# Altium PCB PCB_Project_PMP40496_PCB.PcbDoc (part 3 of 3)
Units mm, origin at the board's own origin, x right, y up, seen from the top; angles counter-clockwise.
Board outline 140 x 100 mm, 4 copper layers (Top Layer, Signal Layer 1, Signal Layer 2, Bottom Layer), stack 1.565 mm thick; 186 components, 128 nets, 605 pads, 270 vias.
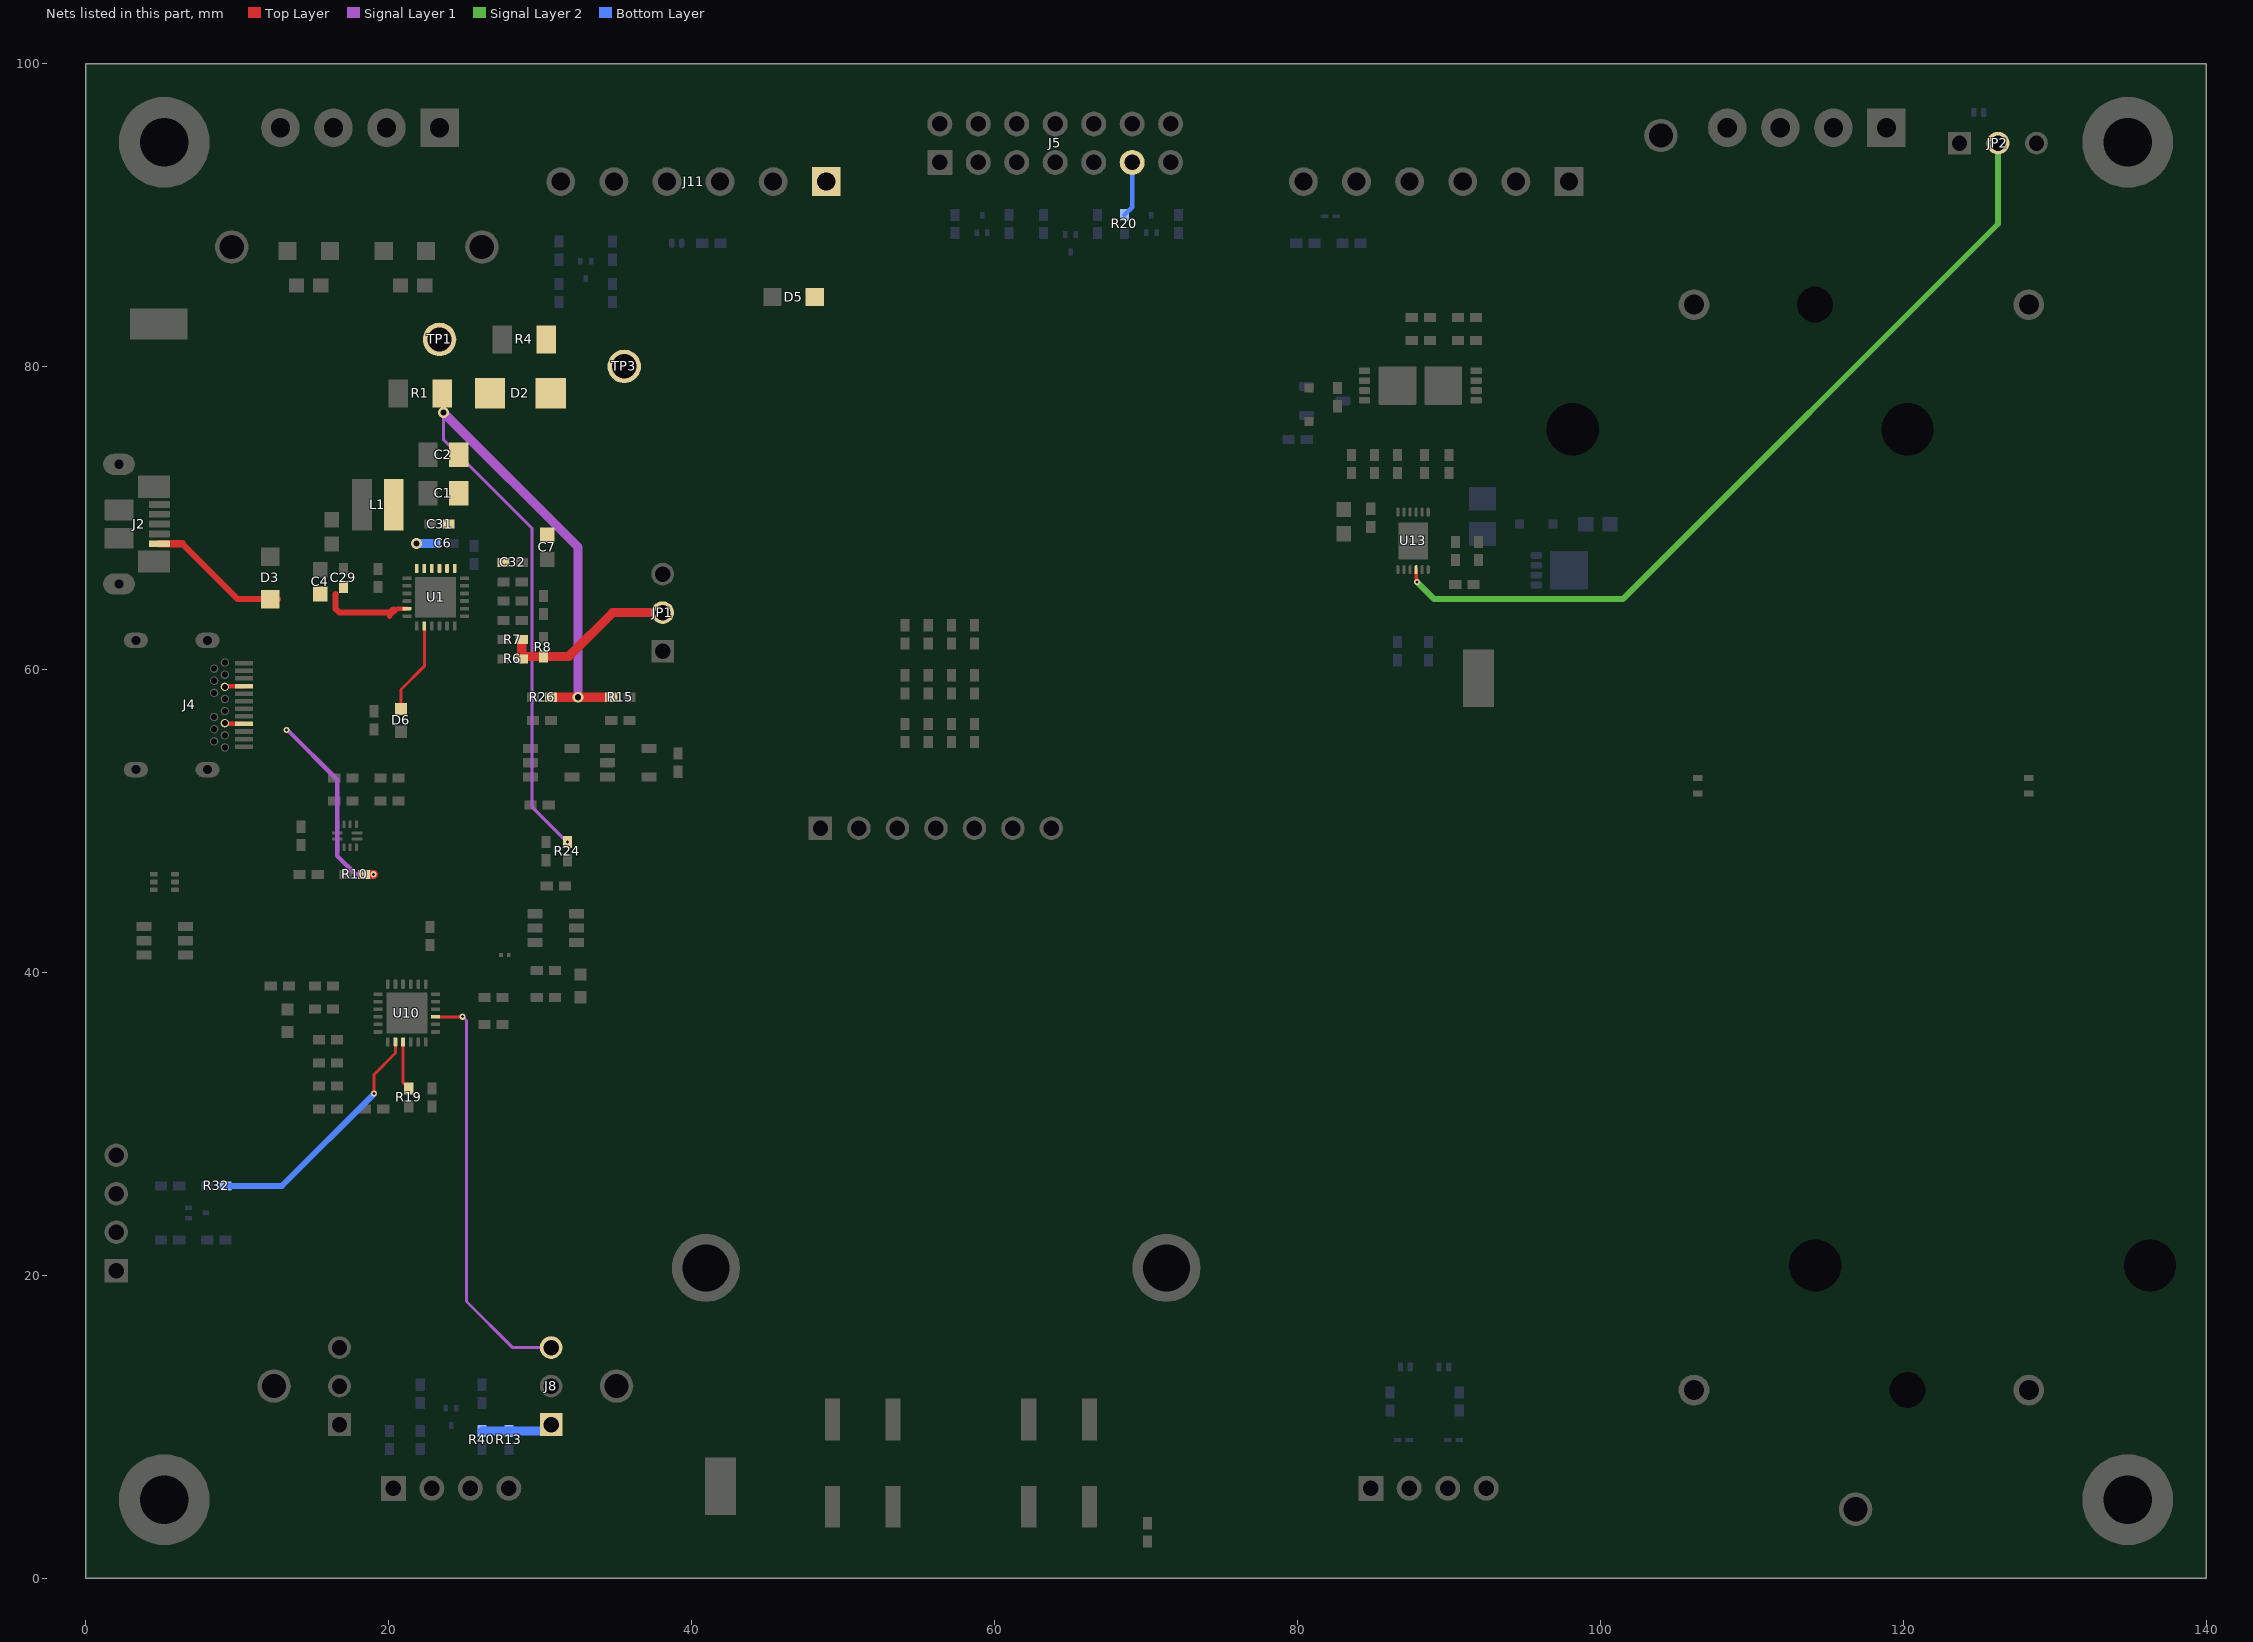
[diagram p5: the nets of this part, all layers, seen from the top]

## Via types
v1: diameter 0.406, hole 0.203, Top Layer to Bottom Layer, 92 vias
v2: diameter 0.711, hole 0.406, Top Layer to Bottom Layer, 89 vias
v3: diameter 0.9, hole 0.6, Top Layer to Bottom Layer, tented top, 59 vias
v4: diameter 0.5, hole 0.2, Top Layer to Bottom Layer, 27 vias
v5: diameter 0.5, hole 0.2, Top Layer to Bottom Layer, tented both sides, 3 vias

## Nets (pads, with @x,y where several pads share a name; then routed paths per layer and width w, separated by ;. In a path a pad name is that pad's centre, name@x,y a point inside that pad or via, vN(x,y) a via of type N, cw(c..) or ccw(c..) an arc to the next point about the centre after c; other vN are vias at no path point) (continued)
SDA_EXT: J8.1 R13.1 R40.2 | length 4.7
  Bottom Layer w0.6: R40.2@26.162,9.744 30.318,9.744 J8.1@30.734,10.16
SDA_MCU: J8.3 U10.9 | length 27.5
  Top Layer w0.2: U10.9@23.109,37.075 24.883,37.075 v1(24.892,37.084)
  Signal Layer 1 w0.2: v1(24.892,37.084) 25.146,36.83 25.146,18.288 28.194,15.24 J8.3@30.734,15.24
STAT: D6.2 U1.2 | length 6.1
  Top Layer w0.2: D6.2@20.828,57.392 20.828,58.674 22.364,60.21 U1.2@22.364,62.87
SW: C6.2 L1.2 U1.17 U1.18 | length 1.2
  Bottom Layer w0.6: v2(21.844,68.326) C6.2@23.022,68.326
TEST: R32.2 U10.2 | length 16.3
  Top Layer w0.2: v1(19.05,32.004) 19.05,33.274 20.459,34.683 U10.2@20.459,35.425
  Bottom Layer w0.4: R32.2@9.236,25.908 12.954,25.908 v1(19.05,32.004)
TS1: JP2.2 U13.4 | length 55.2
  Top Layer w0.22: U13.4@87.83,66.588 87.83,65.84 v1(87.884,65.786)
  Signal Layer 2 w0.4: v1(87.884,65.786) 89.027,64.643 101.473,64.643 126.238,89.408 JP2.2@126.238,94.742
TS_CHG: JP1.2 R6.1 R7.1 R8.2 | length 11.8
  Top Layer w0.6: R7.1@28.794,61.976 R6.1@28.794,60.706 28.956,60.868 R8.2@30.226,60.868 31.912,60.868 34.798,63.754 JP1.2@38.1,63.754
TX: J5.11 R20.1 | length 3.7
  Bottom Layer w0.3: R20.1@68.58,90.008 69.088,90.516 J5.11@69.088,93.472
TX_MCU: R19.2 U10.3 | length 3.2
  Top Layer w0.2: U10.3@20.959,35.425 20.959,32.727 R19.2@21.336,32.35
VBAT: C7.1 C32.1 D2.2 D5.1 J11.1 R4.2 TP3.1 U1.13 U1.14
VBUS: C4.1 C29.1 D3.1 J2.1 J4.A4 J4.A9 J4.B4 J4.B9 R10.1 U1.23 | length 31.5
  Top Layer w0.3: J4.B4@9.193,56.458 9.243,56.408 J4.A9@10.453,56.408 ; J4.B9@9.193,58.858 9.243,58.908 J4.A4@10.453,58.908 ; 20.066,63.5 20.586,64.02 U1.23@21.214,64.02
  Top Layer w0.4: 6.38,68.296 10.036,64.64 D3.1@12.7,64.64 ; 16.51,64.986 16.51,64.008 16.764,63.754 20.104,63.754 20.32,63.97
  Top Layer w0.5: J2.1@4.872,68.296 6.38,68.296
  Top Layer w0.6: R10.1@18.38,46.482 v1(18.999,46.482)
  Signal Layer 1 w0.3: v1(13.271,56.007) 13.335,56.007 16.622,52.72 16.622,47.694 17.834,46.482 v1(18.999,46.482)
VSYS: C1.1 C2.1 C31.1 D2.1 R1.1 R15.1 R24.1 R26.1 TP1.1 U1.15 U1.16 | length 57.9
  Top Layer w0.6: R26.1@30.734,58.166 v2(32.512,58.166) R15.1@34.456,58.166
  Signal Layer 1 w0.2: v2(23.622,76.962) 23.622,75.184 29.464,69.342 29.464,50.949 v1(31.807,48.606)
  Signal Layer 1 w0.6: v2(23.622,76.962) 32.512,68.072 v2(32.512,58.166)
pads on no net: BT1.MH1 BT1.MH2 BT1.MH3 BT2.MH1 BT2.MH2 BT2.MH3 J4.A2 J4.A3 J4.A8 J4.A10 J4.A11 J4.B2 J4.B3 J4.B8 J4.B10 J4.B11 J9.4 J15.4 Q2.9@85.738,78.077 Q2.9@85.738,79.402 Q2.9@86.278,78.74 Q2.9@86.614,78.077 Q2.9@86.614,79.402 Q2.9@87.125,77.765 Q2.9@87.125,78.415 Q2.9@87.125,79.065 Q2.9@87.125,79.715 Q3.9@89.093,77.765 Q3.9@89.093,78.415 Q3.9@89.093,79.065 Q3.9@89.093,79.715 Q3.9@89.604,78.078 Q3.9@89.604,79.403 Q3.9@89.941,78.74 Q3.9@90.48,78.078 Q3.9@90.48,79.403 Q5.9@97.07,65.886 Q5.9@97.07,67.211 Q5.9@97.609,66.548 Q5.9@97.946,65.886 Q5.9@97.946,67.211 Q5.9@98.457,65.573 Q5.9@98.457,66.223 Q5.9@98.457,66.873 Q5.9@98.457,67.523 SH-JP1.0 SH-JP2.0 SH-JP3.0 SH-JP4.0 U1.10 U1.25@22.419,64.075 U1.25@22.419,65.465 U1.25@23.809,64.075 U1.25@23.809,65.465 U4.4 U8.4 U8.5 U10.16 U10.25@20.514,36.63 U10.25@20.514,38.02 U10.25@21.904,36.63 U10.25@21.904,38.02 U15.1S U15.2S U16.1S U16.2S U17.1S U17.2S U18.1S U18.2S

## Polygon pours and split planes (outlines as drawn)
GND on Top Layer "TOP_LAYER_GND_P106" (solid, remove dead copper, pour order 106): 2.505,99.481 71.593,99.481 73.625,97.449 73.625,3.215 71.593,1.183 3.521,1.183 0.473,4.231 0.473,97.449
VBAT on Top Layer "TOP_LAYER_VBAT_P104" (solid, remove dead copper, pour order 104): 44.196,83.312 46.228,83.312 46.736,83.82 46.736,96.52 48.26,98.044 53.086,98.044 54.61,96.52 54.61,75.692 52.832,73.914 44.196,73.914
VBUS on Top Layer "TOP_LAYER_VBUS_P102" (solid, remove dead copper, pour order 102): 5.842,68.58 9.144,68.58 11.938,65.786 17.272,65.786 17.526,65.532 17.526,64.482 17.746,64.262 21.336,64.262 21.59,64.008 21.59,63.754 21.336,63.5 20.706,63.5 20.574,63.368 20.574,61.214 19.558,60.198 17.907,60.198 13.208,55.499 9.906,55.499 9.906,64.008 5.842,68.072
VBAT on Top Layer "TOP_LAYER_VBAT_P094" (solid, remove dead copper, pour order 94): 24.638,67.564 29.21,72.136 29.21,82.296 30.226,83.312 45.212,83.312 45.212,73.914 40.132,73.914 34.544,68.326 28.956,68.326 28.194,67.564
LOAD2 on Top Layer "TOP_LAYER_LOAD2_P092" (solid, remove dead copper, pour order 92): 21.844,98.298 22.606,99.06 28.194,99.06 28.956,98.298 28.956,80.772 28.702,80.518 25.4,80.518 25.146,80.772 25.146,82.989 24.442,83.693 22.733,83.693 21.844,84.582
VSYS on Top Layer "TOP_LAYER_VSYS_P090" (solid, remove dead copper, pour order 90): 23.622,74.168 23.114,74.676 22.352,74.676 21.844,75.184 21.844,82.677 22.479,83.312 24.384,83.312 24.892,82.804 24.892,80.518 25.4,80.01 28.702,80.01 28.956,79.756 28.956,72.136 25.908,69.088 23.622,69.088
LOAD1 on Top Layer "TOP_LAYER_LOAD1_P088" (solid, remove dead copper, pour order 88): 8.382,99.06 13.755,99.06 14.478,98.337 14.478,83.82 17.78,80.518 20.828,80.518 21.59,79.756 21.59,76.708 20.828,75.946 13.462,75.946 7.62,81.788 7.62,98.298
VBAT on Top Layer "TOP_LAYER_VBAT_P086" (solid, remove dead copper, pour order 86): 23.622,66.294 23.622,67.31 24.384,68.072 25.146,68.072 26.416,69.342 28.194,69.342 28.194,67.056 27.94,66.802 25.908,66.802 25.4,66.294
VSYS on Top Layer "TOP_LAYER_VSYS_P084" (solid, remove dead copper, pour order 84): 22.606,66.294 22.606,68.58 23.622,69.596 23.622,74.168 26.162,74.168 26.162,69.342 25.146,68.326 24.638,68.326 23.622,67.31 23.622,66.294
SW on Top Layer "TOP_LAYER_SW_P082" (solid, remove dead copper, pour order 82): 21.712,66.294 21.574,66.294 21.574,66.31 20.32,67.564 20.32,68.072 19.304,69.088 19.304,72.39 19.558,72.644 21.082,72.644 21.336,72.39 21.336,69.85 22.606,68.58 22.606,66.294
GND on Top Layer "TOP_LAYER_GND_P080" (solid, remove dead copper, pour order 80): 20.574,65.278 19.812,66.04 15.494,66.04 15.494,68.834 19.304,68.834 20.066,68.072 20.066,67.564 21.336,66.294 21.844,66.294 21.844,65.278
VBUS on Top Layer "TOP_LAYER_VBUS_P076" (solid, remove dead copper, pour order 76): 15.494,65.786 17.272,65.786 17.272,64.516 17.526,64.262 21.336,64.262 21.59,64.008 21.59,63.754 21.336,63.5 20.574,63.5 19.304,62.23 16.256,62.23 15.494,62.992
PMID on Top Layer "TOP_LAYER_PMID_P074" (solid, remove dead copper, pour order 74): 18.034,66.04 17.78,65.786 17.78,64.516 18.034,64.262 21.336,64.262 21.59,64.516 21.59,65.024 21.336,65.278 20.574,65.278 19.812,66.04
GND1 on Top Layer "TOP_LAYER_GND1_P072" (solid, remove dead copper, pour order 72): 83.312,99.314 81.788,97.79 81.788,3.048 84.074,0.762 137.414,0.762 138.938,2.286 138.938,98.044 137.668,99.314
NetBT1_2 on Top Layer "TOP_LAYER_NETBT1_2_P058" (solid, remove dead copper, pour order 58): 113.03,7.874 114.046,6.858 114.046,3.302 114.808,2.54 118.872,2.54 119.634,3.302 119.634,6.858 120.65,7.874
NetBT1_1 on Top Layer "TOP_LAYER_NETBT1_1_P002" (solid, remove dead copper, pour order 2): 92.202,79.248 92.456,79.502 92.456,80.264 91.44,81.28 91.44,84.836 92.964,86.36 107.413,86.36 109.728,84.045 109.728,77.216 108.458,75.946 92.456,75.946 91.44,76.962 91.44,78.994 91.694,79.248
NetBT1_2 on Top Layer "TOP_LAYER_NETBT1_2_P004" (solid, remove dead copper, pour order 4): 104.14,18.796 128.27,18.796 130.556,16.51 130.556,8.636 129.54,7.62 103.378,7.62 102.362,8.636 102.362,17.018
NetBT1_1 on Top Layer "TOP_LAYER_NETBT1_1_P006" (solid, remove dead copper, pour order 6): 101.092,99.314 108.966,99.314 109.728,98.552 109.728,87.122 109.728,86.106 109.728,83.786 99.06,83.851 99.06,86.106 100.33,87.376 100.33,98.552
NetQ2_5 on Top Layer "TOP_LAYER_NETQ2_5_P022" (solid, remove dead copper, pour order 22): 85.344,80.264 90.678,80.264 90.932,80.01 90.932,77.47 90.678,77.216 85.344,77.216 85.09,77.47 85.09,80.01
NetQ2_4 on Top Layer "TOP_LAYER_NETQ2_4_P030" (solid, remove dead copper, pour order 30): 82.296,77.978 84.836,77.978 84.836,76.708 82.296,76.708 82.042,76.962 82.042,77.724
PACK+ on Top Layer "TOP_LAYER_PACK+_P038" (solid, remove dead copper, pour order 38): 77.216,97.79 78.74,99.314 88.9,99.314 89.916,98.298 89.916,84.582 89.408,84.074 88.532,84.074 84.831,80.373 84.831,78.481 84.535,78.185 77.855,78.185 77.216,78.824
NetBT1_2 on Top Layer "TOP_LAYER_NETBT1_2_P040" (solid, remove dead copper, pour order 40): 110.236,98.552 110.998,99.314 116.078,99.314 117.094,98.298 117.094,93.726 123.444,87.376 123.444,81.28 111.252,81.28 110.236,82.296
NetBT1_2 on Top Layer "TOP_LAYER_NETBT1_2_P044" (solid, pour order 44): 111.252,81.28 111.252,20.574 108.966,18.288 126.492,18.288 123.444,21.336 123.444,81.28
GND2 on Top Layer "TOP_LAYER_GND2_P048" (solid, remove dead copper, pour order 48): 127.762,52.324 129.032,52.324 129.286,52.07 129.286,51.562 129.032,51.308 127.762,51.308 127.508,51.562 127.508,52.07
NetJP2_3 on Top Layer "TOP_LAYER_NETJP2_3_P050" (solid, remove dead copper, pour order 50): 128.143,95.631 129.413,95.631 129.667,95.377 129.667,94.107 129.54,93.98 128.016,93.98 127.889,94.107 127.889,95.377
TS1 on Top Layer "TOP_LAYER_TS1_P052" (solid, remove dead copper, pour order 52): 125.603,95.631 126.873,95.631 127.127,95.377 127.127,94.107 127,93.98 125.476,93.98 125.349,94.107 125.349,95.377
PMID on Top Layer "TOP_LAYER_PMID_P114" (solid, remove dead copper, pour order 114): 17.272,72.644 18.796,72.644 19.05,72.39 19.05,69.342 18.796,69.088 15.748,69.088 15.494,69.342 15.494,70.866
PMID on Bottom Layer "BOTTOM_LAYER_PMID_P098" (solid, remove dead copper, pour order 98): 17.272,72.644 20.32,72.644 20.574,72.39 20.574,64.629 20.207,64.262 17.78,64.262 17.526,64.516 17.526,68.326 16.764,69.088 16.764,72.136
GND1 on Bottom Layer "BOTTOM_LAYER_GND1_P070" (solid, remove dead copper, pour order 70): 78.74,70.358 81.788,67.31 81.788,3.048 84.074,0.762 137.414,0.762 138.938,2.286 138.938,98.044 137.668,99.314
NetR72_2 on Bottom Layer "BOTTOM_LAYER_NETR72_2_P068" (solid, remove dead copper, pour order 68): 90.17,11.938 89.916,12.192 89.916,13.97 90.17,14.224 91.186,14.224 91.44,13.97 91.44,12.192 91.186,11.938
NetR74_2 on Bottom Layer "BOTTOM_LAYER_NETR74_2_P066" (solid, remove dead copper, pour order 66): 85.598,11.938 85.344,12.192 85.344,13.97 85.598,14.224 86.614,14.224 86.868,13.97 86.868,12.192 86.614,11.938
SDA1 on Bottom Layer "BOTTOM_LAYER_SDA1_P064" (solid, remove dead copper, pour order 64): 89.154,4.826 88.9,5.08 88.9,8.382 89.154,8.636 90.932,8.636 90.932,9.525 89.662,9.525 89.662,11.176 89.916,11.43 91.694,11.43 91.948,11.176 91.948,7.62 91.186,6.858 91.186,5.08 90.932,4.826
SCL1 on Bottom Layer "BOTTOM_LAYER_SCL1_P062" (solid, remove dead copper, pour order 62): 87.884,4.826 88.392,5.334 88.392,8.382 88.138,8.636 86.487,8.636 86.36,8.763 86.36,9.525 87.63,9.525 87.63,11.176 87.376,11.43 85.598,11.43 85.344,11.176 85.344,7.874 86.106,7.112 86.106,5.334 86.614,4.826
NetBT2_2 on Bottom Layer "BOTTOM_LAYER_NETBT2_2_P008" (solid, remove dead copper, pour order 8): 114.3,99.06 116.332,99.06 117.094,98.298 117.094,93.472 118.364,92.202 130.048,92.202 133.604,88.646 133.604,80.518 131.572,78.486 118.274,78.486 115.57,81.19 115.57,84.328 113.792,86.106 113.792,98.552
NetBT2_2 on Bottom Layer "BOTTOM_LAYER_NETBT2_2_P012" (solid, remove dead copper, pour order 12): 96.52,67.818 97.028,68.326 101.092,68.326 108.712,75.946 108.712,87.63 120.142,87.63 120.142,78.74 118.618,77.216 118.618,70.612 113.03,65.024 97.028,65.024 96.52,65.532
NetBT2_2 on Bottom Layer "BOTTOM_LAYER_NETBT2_2_P014" (solid, pour order 14): 108.712,88.392 113.792,93.472 115.824,93.472 115.824,87.122 108.712,87.122
GND2 on Bottom Layer "BOTTOM_LAYER_GND2_P016" (solid, remove dead copper, pour order 16): 94.488,69.85 94.996,69.342 94.996,67.31 95.25,67.056 96.012,67.056 96.266,66.802 96.266,65.278 96.012,65.024 90.932,65.024 90.678,65.278 90.678,69.596 90.932,69.85
GND2 on Bottom Layer "BOTTOM_LAYER_GND2_P020" (solid, remove dead copper, pour order 20): 86.614,69.596 86.868,69.85 91.17,69.85 91.17,67.2 86.756,67.198 86.614,67.34
NetQ2_5 on Bottom Layer "BOTTOM_LAYER_NETQ2_5_P028" (solid, remove dead copper, pour order 28): 85.344,80.264 90.678,80.264 90.932,80.01 90.932,77.47 90.678,77.216 85.344,77.216 85.09,77.47 85.09,80.01
PACK+ on Bottom Layer "BOTTOM_LAYER_PACK+_P034" (solid, pour order 34): 78.74,93.726 81.28,93.726 81.534,93.472 81.534,89.154 81.083,88.703 80.829,88.703 80.518,88.392 80.518,87.884 80.264,87.63 78.994,87.63 78.486,88.138 78.486,93.472
GND1 on Bottom Layer "BOTTOM_LAYER_GND1_P036" (solid, remove dead copper, pour order 36): 100.584,70.104 106.426,75.946 106.426,98.044 105.156,99.314 78.74,99.314 77.216,97.79 77.216,71.882 78.994,70.104
GND2 on Bottom Layer "BOTTOM_LAYER_GND2_P046" (solid, remove dead copper, pour order 46): 90.678,65.278 90.678,57.658 90.932,57.404 95.592,57.404 96.266,58.078 96.266,65.278
NetJ14_1 on Bottom Layer "BOTTOM_LAYER_NETJ14_1_P054" (solid, remove dead copper, pour order 54): 123.063,95.631 124.333,95.631 124.587,95.377 124.587,94.107 124.46,93.98 122.936,93.98 122.809,94.107 122.809,95.377
NetJ14_1 on Bottom Layer "BOTTOM_LAYER_NETJ14_1_P056" (solid, remove dead copper, pour order 56): 122.428,97.028 122.682,97.282 124.46,97.282 124.714,97.028 124.714,94.234 124.46,93.98 122.682,93.98 122.428,94.234
GND on Bottom Layer "BOTTOM_LAYER_GND_P126" (solid, remove dead copper, pour order 126): 2.505,99.481 71.593,99.481 73.625,97.449 73.625,3.215 71.593,1.183 3.521,1.183 0.473,4.231 0.473,97.449
no net on Top Overlay "NONET_L-01_P-001" (hatched 45Degree grid 1 track 0.2, remove dead copper): 74.168,99.924 77.216,99.924 77.216,-0.13 74.168,-0.13
NetQ2_5 on Signal Layer 1 "SIGNAL_LAYER_1_NETQ2_5_P024" (solid, remove dead copper, pour order 24): 85.344,80.264 90.678,80.264 90.932,80.01 90.932,77.47 90.678,77.216 85.344,77.216 85.09,77.47 85.09,80.01
GND on Signal Layer 1 "SIGNAL_LAYER_1_GND_P122" (solid, remove dead copper, pour order 122): 2.505,99.481 71.593,99.481 73.625,97.449 73.625,3.215 71.593,1.183 3.521,1.183 0.473,4.231 0.473,97.449
NetQ2_5 on Signal Layer 2 "SIGNAL_LAYER_2_NETQ2_5_P000" (solid, remove dead copper, pour order 0): 85.344,80.264 90.678,80.264 90.932,80.01 90.932,77.47 90.678,77.216 85.344,77.216 85.09,77.47 85.09,80.01
GND on Signal Layer 2 "SIGNAL_LAYER_2_GND_P124" (solid, remove dead copper, pour order 124): 2.505,99.481 71.593,99.481 73.625,97.449 73.625,3.215 71.593,1.183 3.521,1.183 0.473,4.231 0.473,97.449
no net on Bottom Overlay "NONET_L-01_P-001" (hatched 45Degree grid 1 track 0.2, remove dead copper): 74.168,99.992 77.216,99.992 77.216,59.376 74.168,59.376

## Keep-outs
Keep-Out Layer:
  text ".Layer_Name" at 14.656,-21.806 h1.52

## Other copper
Top Layer:
  pour cut-out: 90.424,75.692 111.001,75.692 111.048,75.74 111.048,64.551 90.459,64.551 90.424,64.516
  text ".Layer_Name" at 14.656,-21.806 h1.52
Signal Layer 1:
  pour cut-out: 6.528,45.086 6.858,44.756 6.858,43.18 6.223,42.545 4.318,42.545 3.683,43.18 3.683,44.705 4.064,45.086
  pour cut-out: 69.215,96.901 69.215,98.425 68.326,99.314 29.972,99.314 22.606,91.948 15.621,91.948 8.255,84.582 8.255,73.533 4.064,69.342 4.064,45.086 6.528,45.086 6.528,67.615 11.176,72.263 11.176,82.169 18.034,89.027 23.622,89.027 23.622,89.154 31.514,97.046 69.088,97.046
Signal Layer 2:
  pour cut-out: 4.318,60.198 6.388,60.198 6.731,59.855 6.731,59.182 7.239,58.674 12.065,58.674 12.818,57.921 12.818,56.932 11.541,55.655 5.807,55.661 3.937,57.531 3.937,59.817
Bottom Layer:
  text ".Layer_Name" at 14.656,-21.806 h1.52

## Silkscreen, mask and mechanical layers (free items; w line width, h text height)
Top Overlay:
  lines w0.254: 38.448,18.002 73.914,18.002 ; 38.448,18.096 38.448,51.53 73.914,51.53 73.914,18.03 ; 10.922,44.196 24.892,44.196 24.892,53.848 10.922,53.848 10.922,44.196 ; 14.478,59.182 14.478,75.692 34.798,75.692 34.798,59.182 14.478,59.182 ; 78.994,64.516 93.472,64.516 93.472,84.074 78.994,84.074 78.994,64.516
  text "TS" at 126.619,91.567 h1 r90
  text "CELL2" at 101.346,90.678 h1.85
  text "LOAD1<6A" at 7.366,89.916 h1.6
  text "LOAD2>6A" at 23.368,89.916 h1.6
  text "NTC_INT" at 129.032,89.408 h1 r90
  text "NTC_EXT" at 124.079,89.154 h1 r90
  text "GND" at 17.018,88.9 h1.85 r90
  text "GND" at 20.32,88.9 h1.85 r90
  text "D-" at 67.043,88.646 h1.85 r90
  text "D+" at 69.85,88.646 h1.85 r90
  text "VSS" at 116.078,88.392 h1.85 r90
  text "NTC" at 119.634,88.392 h1.85 r90
  text "SCL" at 61.963,88.189 h1.85 r90
  text "SDA" at 64.529,88.189 h1.85 r90
  text "ID_C" at 56.896,87.884 h1.85 r90
  text "VCC" at 72.39,87.884 h1.85 r90
  text "-" at 127.762,87.884 h4
  text "INT_C" at 59.436,87.63 h1.85 r90
  text "+" at 105.41,87.63 h3.5
  text "CELL2" at 108.966,87.63 h1.85 r90
  text "CELL1" at 112.522,87.63 h1.85 r90
  text "SCL" at 96.52,87.376 h1.85
  text "SCL" at 32.258,86.106 h1.85 r90
  text "SDA" at 35.814,86.106 h1.85 r90
  text "GND" at 39.37,86.106 h1.85 r90
  text "NTC" at 42.926,86.106 h1.85 r90
  text "GND" at 46.482,86.106 h1.85 r90
  text "VBAT" at 49.53,85.598 h1.85 r90
  text "NTC+" at 87.884,85.09 h1.85 r90
  text "NTC-" at 91.44,85.09 h1.85 r90
  text "SDA" at 94.996,85.09 h1.85 r90
  text "PGND" at 2.54,84.582 h1.85
  text "PACK+" at 81.026,84.582 h1.85 r90
  text "PACK-" at 84.582,84.582 h1.85 r90
  text "INT" at 61.976,84.328 h1.85 r90
  text "ID_B" at 64.516,84.074 h1.85 r90
  text "TX" at 69.85,84.074 h1.85 r90
  text "RX" at 72.39,84.074 h1.85 r90
  text "GND" at 56.896,83.82 h1.85 r90
  text "GND" at 59.436,83.82 h1.85 r90
  text "GND" at 67.056,83.82 h1.85 r90
  text "VSYS" at 17.018,80.264 h1.85
  text "VBAT" at 37.592,78.994 h1.85
  text "PMP40496" at 56.642,75.946 h3
  text "Rev.1.0" at 61.976,73.66 h2.5
  text "10K" at 40.005,66.04 h1
  text "TS" at 40.005,63.373 h1
  text "Gauge & Protector" at 78.994,63.246 h1.5
  text "NTC_EXT" at 39.878,60.96 h1
  text "Boost Charger" at 14.732,59.69 h1.5
  text "CC Logic" at 11.43,54.229 h1.5
  text "GND2" at 90.043,54.102 h1.85
  text "OLED SCREEN" at 49.784,45.942 h1.85
  text "VCC" at 4.064,27.178 h1.85
  text "TEST" at 3.81,24.638 h1.85
  text "RST" at 4.064,22.098 h1.85
  text "GND" at 4.064,19.558 h1.85
  text "SCL" at 10.922,14.986 h1.85
  text "SDA" at 33.274,14.986 h1.85
  text "SCL_MCU" at 18.288,14.859 h1
  text "SDA_MCU" at 24.892,14.859 h1
  text "SCL" at 18.288,12.7 h1
  text "SDA" at 24.892,12.7 h1
  text "Reset" at 49.53,12.7 h1.85
  text "Screen ON/OFF" at 58.928,12.7 h1.85
  text "SCL_EXT" at 18.288,11.049 h1
  text "SDA_EXT" at 24.892,11.049 h1
  text "AGND" at 39.624,9.144 h1.85
  text "GND" at 21.082,7.366 h1.85 r90
  text "SCL" at 23.368,7.366 h1.85 r90
  text "SDA" at 25.908,7.366 h1.85 r90
  text "PACK-" at 85.598,7.366 h1.85 r90
  text "SCL" at 88.138,7.366 h1.85 r90
  text "SDA" at 90.678,7.366 h1.85 r90
  text "-" at 105.918,6.604 h4
  text "+" at 127.762,6.604 h3.5
  text "CELL1" at 109.982,3.302 h1.85
  text ".Layer_Name" at 14.656,-21.806 h1.52
Bottom Overlay:
  text ".Layer_Name" at 14.656,-21.806 h1.52
Top Paste:
  text ".Layer_Name" at 14.656,-21.806 h1.52
Bottom Paste:
  text ".Layer_Name" at 14.656,-21.806 h1.52
Top Solder:
  text ".Layer_Name" at 14.656,-21.806 h1.52
  text ".Layer_Name" at 14.656,-21.806 h1.52
Bottom Solder:
  text ".Layer_Name" at 14.656,-21.806 h1.52
Drill Guide:
  text ".Layer_Name" at 14.656,-21.806 h1.52
M1 Board Outline:
  the board outline again, w0.254
  text ".Layer_Name" at 14.656,-21.806 h1.52
M2 Board Dimensions:
  rectangle: 0,-6.985 3.175,-3.81
  rectangle: 3.175,-10.16 12.7,-6.985
  lines w0.178: 0,-6.985 25.4,-6.985 ; 3.175,-10.16 3.175,-3.81 ; 6.35,-10.16 6.35,-3.81 ; 12.7,-10.16 12.7,-3.81 ; 19.05,-10.16 19.05,-3.81 ; 0,-10.16 25.4,-10.16 25.4,-3.81 0,-3.81 0,-10.16
  text ".Layer_Name" at 14.656,-21.806 h1.52
M3 3D STEP Top:
  text ".Layer_Name" at 14.656,-21.806 h1.52
M4 3D STEP Bottom:
  text ".Layer_Name" at 14.656,-21.806 h1.52
M5 Assembly Top:
  lines w0.254: -7.417,-23.626 160.223,-23.626 ; -7.417,-18.462 160.274,-18.462 ; -7.417,-13.297 -7.417,-28.791 94.31,-28.791 160.274,-28.791 160.274,-13.297 -7.404,-13.297 -7.404,-28.791 32.614,-28.791 ; 55.194,-28.791 55.194,-13.297 ; 87.376,-18.462 87.376,-13.297 ; 108.712,-18.462 108.712,-13.297 ; 124.511,-28.956 124.511,-23.804
  text "COMPONENTS MARKED 'DNP' SHOULD NOT BE POPULATED." at 29.299,-8.09 h1.52
  text "ASSEMBLY VARIANT:" at 29.286,-11.024 h1.52
  text ".VariantName" at 55.601,-11.024 h1.52
  text "PCB VIEWED FROM TOP SIDE" at -5.804,-16.654 h1.52
  text "BOARD #:" at 57.099,-16.654 h1.52
  text ".PRJ_Number" at 70.955,-16.654 h1.52
  text "REV:" at 92.405,-16.654 h1.52
  text ".PCB_Rev" at 99.809,-16.654 h1.52
  text "SVN REV:" at 113.69,-16.654 h1.52
  text ".VersionControl_RevNumber" at 126.543,-16.654 h1.52
  text "TID #:" at 57.099,-21.819 h1.52
  text ".TID" at 70.955,-21.819 h1.52
  text "PLOT NAME =" at -5.804,-27.034 h1.52
  text ".plot_File_Name" at 14.656,-27.034 h1.52
  text "GENERATED    :" at 57.15,-27.034 h1.52
  text ".Print_Date" at 79.235,-27.034 h1.52
  text ".Print_Time" at 97.752,-27.034 h1.52
  text "TEXAS INSTRUMENTS" at 129.87,-27.034 h1.52
M6 Assembly Bottom:
  lines w0.254: -7.429,-18.474 160.261,-18.474 ; -7.379,-23.639 160.261,-23.639 ; 28.334,-28.969 28.334,-23.817 ; 44.133,-18.474 44.133,-13.31 ; 65.468,-18.474 65.468,-13.31 ; 97.65,-28.804 97.65,-13.31 ; 120.231,-28.804 160.249,-28.804 160.249,-13.31 -7.429,-13.31 -7.429,-28.804 58.534,-28.804 160.261,-28.804 160.261,-13.31
  text "COMPONENTS MARKED 'DNP' SHOULD NOT BE POPULATED." at 154.991,-8.077 h1.52
  text ".VariantName" at 128.473,-11.024 h1.52
  text "ASSEMBLY VARIANT:" at 154.864,-11.024 h1.52
  text ".VersionControl_RevNumber" at 26.302,-16.667 h1.52
  text "SVN REV:" at 39.154,-16.667 h1.52
  text ".PCB_Rev" at 53.035,-16.667 h1.52
  text "REV:" at 60.439,-16.667 h1.52
  text ".PRJ_Number" at 81.89,-16.667 h1.52
  text "BOARD #:" at 95.745,-16.667 h1.52
  text "PCB VIEWED FROM BOTTOM SIDE" at 158.648,-16.667 h1.52
  text ".TID" at 81.89,-21.831 h1.52
  text "TID #:" at 95.745,-21.831 h1.52
  text "TEXAS INSTRUMENTS" at 22.974,-27.047 h1.52
  text ".Print_Time" at 55.093,-27.047 h1.52
  text ".Print_Date" at 73.609,-27.047 h1.52
  text "GENERATED    :" at 95.694,-27.047 h1.52
  text ".plot_File_Name" at 138.189,-27.047 h1.52
  text "PLOT NAME =" at 158.648,-27.047 h1.52
M9 Title Sheet:
  drawing of 57 lines, arcs and shapes, not listed
  text "1" at 18.792,204.127 h1.78
  text "2" at 82.182,204.127 h1.78
  text "3" at 145.411,204.127 h1.78
  text "4" at 209.08,204.127 h1.78
  text "5" at 272.555,204.127 h1.78
  text "6" at 336.182,204.127 h1.78
  text "A" at -10.579,175.095 h1.78
  text "A" at 365.341,175.095 h1.78
  text "B" at -10.579,114.643 h1.78
  text "B" at 365.341,114.643 h1.78
  text "C" at -10.579,54.318 h1.78
  text "C" at 365.341,54.318 h1.78
  text "PROJECT TITLE:" at 288.125,7.048 h1.14
  text ".PRJ_Title" at 289.395,3.662 h1.78
  text "DESIGNED FOR:" at 288.125,-0.597 h1.14
  text ".PRJ_Customer" at 289.395,-4.153 h1.78
  text "D" at -10.579,-5.88 h1.78
  text "D" at 365.341,-5.88 h1.78
  text "FILE NAME:" at 288.125,-8.217 h1.14
  text ".PCB_File_Name_No_Path" at 289.395,-11.265 h1.78
  text "Texas Instruments (TI) and/or its licensors do not warrant the accuracy or completeness of this specification" at 161.9,-15.376 h1.14
  text "ENGINEER:" at 288.125,-15.583 h1.14
  text "LAYOUT BY:" at 326.352,-15.583 h1.14
  text "or any information contained therein. TI and/or its licensors do not warrant that this design will meet" at 160.757,-18.237 h1.14
  text ".PRJ_Engineer" at 289.395,-19.52 h1.78
  text ".PCB_Layout" at 327.635,-19.52 h1.78
  text "the specifications, will be suitable for your application or fit for any particular purpose, or will operate in" at 160.757,-21.099 h1.14
  text ".Layer_Name" at 14.656,-21.806 h1.52
  text "ALTIUM DESIGNER VERSION:" at 326.352,-23.457 h1.14
  text "an implementation. TI and/or its licensors do not warrant that the design is production worthy. You should" at 160.757,-23.961 h1.14
  text "completely validate and test your design implementation to confirm the system functionality for your application." at 161.9,-26.822 h1.14
  text ".print_Scale" at 289.395,-26.843 h1.78
  text ".Application_BuildNumber" at 327.635,-26.843 h1.78
  text "1" at 18.792,-32.093 h1.78
  text "2" at 82.182,-32.093 h1.78
  text "3" at 145.411,-32.093 h1.78
  text "4" at 209.08,-32.093 h1.78
  text "5" at 272.555,-32.093 h1.78
  text "6" at 336.182,-32.093 h1.78
M10 Fab Notes:
  drawing of 189 lines, arcs and shapes, not listed
  text "DESIGN INFORMATION" at 314.503,161.447 h1.52
  text "MIN. TRACK WIDTH:" at 298.131,158.091 h1.52
  text "8" at 325.976,158.091 h1.52
  text "MIL" at 329.907,158.091 h1.52
  text "MIN. CLEARANCE:" at 298.131,154.938 h1.52
  text "0.2" at 324.452,154.938 h1.52
  text "mm" at 329.907,154.938 h1.52
  text "MIN. VIA PAD SIZE:" at 298.131,151.785 h1.52
  text "24" at 325.214,151.785 h1.52
  text "MIL" at 329.907,151.785 h1.52
  text "0.05mm (2MIL)" at 315.784,148.486 h1.52
  text "MINIMUM ANNULAR RING" at 289.769,148.277 h1.52
  text "EXTERNAL" at 333.768,148.277 h1.52
  text "PER" at 294.849,145.48 h1.52
  text "IPC-D-275 CLASS 2 LEVEL C" at 300.437,145.48 h1.52
  text "MIL, HOLES" at 338.238,142.928 h1.52
  text "+/-" at 328.27,142.709 h1.52
  text "+/-" at 349.961,142.709 h1.52
  text "REGISTRATION TOLERANCES:" at 289.769,142.682 h1.52
  text "METAL" at 320.243,142.682 h1.52
  text "5" at 334.879,142.683 h1.52
  text "3" at 356.037,142.683 h1.52
  text "MIL" at 358.99,142.682 h1.52
  text "HOLE SIZE TOLERANCE (UNLESS OTHERWISE SPECIFIED):" at 289.769,140.185 h1.52
  text "+/-" at 349.961,140.112 h1.52
  text "3" at 356.037,140.085 h1.52
  text "MIL" at 358.99,140.085 h1.52
  text "MATERIAL:" at 287.87,136.589 h1.52
  text "FR-4 High Tg" at 312.926,133.324 h1.52
  text "X" at 309.257,133.122 h1.52
  text "FR-408" at 298.563,133.007 h1.52
  text "OTHER" at 336.358,133.007 h1.52
  text "62 MIL (1.6mm) +/-10%" at 306.694,129.374 h1.52
  text "X" at 303.643,129.312 h1.52
  text "THICKNESS:" at 289.769,129.165 h1.52
  text "OTHER" at 339.33,129.165 h1.52
  text "TOLERANCE:" at 289.769,125.652 h1.52
  text "X" at 311.314,125.652 h1.52
  text "ANSI IPC-6012 TYPE 3 CLASS 2" at 315.836,125.652 h1.52
  text "OTHER +/-" at 315.835,121.989 h1.52
  text "BOW & TWIST:" at 289.769,118.302 h1.52
  text "X" at 311.314,118.302 h1.52
  text "ANSI IPC-6012 TYPE 3 CLASS 2" at 315.836,118.302 h1.52
  text "OTHER +/-" at 315.835,114.576 h1.52
  text "DRILLING:" at 287.87,111.258 h1.52
  text "NC_DRILL FILES" at 332.599,108.586 h1.52
  text "REFERENCE:" at 289.769,108.486 h1.52
  text "X" at 306.463,108.484 h1.52
  text "AS SHOWN" at 310.984,108.486 h1.52
  text "X" at 329.348,108.486 h1.52
  text "OTHER" at 340.168,104.873 h1.52
  text "PTH COPPER THICKNESS:" at 289.761,104.783 h1.52
  text "X" at 318.697,104.783 h1.52
  text "20-30 um" at 321.948,104.783 h1.52
  text "BOARD FINISH:" at 287.87,101.034 h1.52
  text "SILKSCREEN:" at 291.812,98.237 h1.52
  text "X" at 316.14,98.237 h1.52
  text "TOP" at 319.112,98.237 h1.52
  text "X" at 329.094,98.237 h1.52
  text "BOTTOM" at 332.091,98.237 h1.52
  text "SILKSCREEN COLOR:" at 291.812,94.295 h1.52
  text "X" at 316.115,94.295 h1.52
  text "WHITE" at 319.112,94.295 h1.52
  text "OTHER" at 332.091,94.295 h1.52
  text "X" at 319.442,90.652 h1.52
  text "GREEN" at 322.439,90.652 h1.52
  text "OTHER" at 338.136,90.652 h1.52
  text "SOLDER RESIST COLOR:" at 291.812,90.477 h1.52
  text "X" at 319.442,86.734 h1.52
  text "MATTE" at 322.439,86.734 h1.52
  text "SEMI-GLOSS" at 338.125,86.717 h1.52
  text "IMMERSION GOLD (ENIG)" at 314.819,82.345 h1.52
  text "ENEPIG" at 348.793,82.162 h1.52
  text "SURFACE FINISH:" at 287.87,82.136 h1.52
  text "X" at 310.298,82.136 h1.52
  text "IMM. TIN/SILVER OR EQUIV" at 296.24,78.649 h1.52
  text "OTHER" at 332.599,78.549 h1.52
  text "ARRAY/PANEL:" at 287.87,74.602 h1.52
  text "CUT AND TRIM PER M1 BOARD OUTLINE" at 314.819,74.393 h1.52
  text "N.C. ROUTE" at 314.819,70.94 h1.52
  text "X" at 332.295,70.94 h1.52
  text "V. SCORE" at 336.816,70.94 h1.52
  text "CERTIFICATION:" at 287.87,67.66 h1.52
  text "MATERIALS AND WORKMANSHIP FOR ALL PCBS" at 306.285,67.66 h1.52
  text "TO MEET OR EXCEED THE REQUIREMENTS OF:" at 306.285,65.271 h1.52
  text "X" at 297.078,62.003 h1.52
  text "ANSI IPC-A-600F CLASS ->" at 300.329,62.003 h1.52
  text "X" at 342.188,62.003 h1.52
  text "2" at 344.982,62.003 h1.52
  text "1" at 336.981,61.965 h1.52
  text "3" at 353.973,61.965 h1.52
  text "X" at 317.702,58.252 h1.52
  text "RoHS" at 320.953,58.252 h1.52
  text "OTHER" at 337.321,58.252 h1.52
  text "PER ORDER" at 347.407,58.252 h1.52
  text "ALL BOARDS MUST MEET OR EXCEED UL94-V0 REQUIREMENTS." at 288.569,54.345 h1.52
  text "PCB MUST BEAR THE UL94V-0 UL REGISTERED MATERIAL ID NUMBER" at 288.569,51.397 h1.52
  text "ADDITIONAL REQUIREMENTS:" at 287.87,47.094 h1.52
  text "MICROSECTION:" at 289.769,44.373 h1.52
  text "YES" at 312.775,44.373 h1.52
  text "REQUIRED" at 334.657,40.707 h1.52
  text "BARE BOARD ELEC. TEST:" at 289.769,40.634 h1.52
  text "NONE" at 322.935,40.634 h1.52
  text "X" at 331.66,40.634 h1.52
  text "PER ORDER" at 349.693,40.634 h1.52
  text "XX MIL VIAS REQUIRE NON-CONDUCTIVE FILL AND PLANARIZE" at 294.04,35.428 h1.5
  text "XX MIL VIAS REQUIRE CONDUCTIVE FILL AND PLANARIZE" at 294.243,32.787 h1.52
  text "OUTER XX MIL TRACES REQUIRE 50 OHM SINGLE-ENDED IMPEDANCE" at 294.218,28.637 h1.47
  text "LAYER 2 & 3 (INNER LAYERS) XX MIL WIDE, XX MIL SPACE / TRACES REQUIRE 100 OHM DIFFERENTIAL IMPEDANCE" at 294.015,22.65 h1.52
  text ".Layer_Name" at 14.656,-21.806 h1.52
M11 Gerber Information:
  lines w0.254: -7.417,-23.626 160.223,-23.626 ; -7.417,-18.462 160.274,-18.462 ; -7.417,-13.297 -7.417,-28.791 94.31,-28.791 160.274,-28.791 160.274,-13.297 -7.404,-13.297 -7.404,-28.791 32.614,-28.791 ; 55.194,-28.791 55.194,-13.297 ; 87.376,-18.462 87.376,-13.297 ; 108.712,-18.462 108.712,-13.297 ; 124.511,-28.956 124.511,-23.804
  text "ALL ARTWORK VIEWED FROM TOP SIDE" at -5.804,-16.654 h1.52
  text "BOARD #:" at 57.099,-16.654 h1.52
  text ".PRJ_Number" at 70.955,-16.654 h1.52
  text "REV:" at 92.405,-16.654 h1.52
  text ".PCB_Rev" at 99.809,-16.654 h1.52
  text "SVN REV:" at 113.69,-16.654 h1.52
  text ".VersionControl_RevNumber" at 126.543,-16.654 h1.52
  text "LAYER NAME =" at -5.804,-21.806 h1.52
  text "TID #:" at 57.099,-21.819 h1.52
  text ".TID" at 70.955,-21.819 h1.52
  text "PLOT NAME =" at -5.804,-27.034 h1.52
  text ".plot_File_Name" at 14.656,-27.034 h1.52
  text "GENERATED    :" at 57.15,-27.034 h1.52
  text ".Print_Date" at 79.235,-27.034 h1.52
  text ".Print_Time" at 97.752,-27.034 h1.52
  text "TEXAS INSTRUMENTS" at 129.87,-27.034 h1.52
M12 Stackup:
  drawing of 295 lines, arcs and shapes, not listed
  text "Layer" at 248.865,198.882 h1.52
  text "Name" at 259.277,198.882 h1.52
  text "Material" at 283.146,198.882 h1.52
  text "Thickness" at 304.985,198.882 h1.52
  text "Constant" at 321.49,198.882 h1.52
  text "Board Layer Stack" at 335.965,198.882 h1.52
  text "1" at 248.865,195.834 h1.52
  text "Top Overlay" at 259.277,195.834 h1.52
  text "2" at 248.865,192.786 h1.52
  text "Top Solder" at 259.277,192.786 h1.52
  text "Solder Resist" at 283.146,192.786 h1.52
  text "0.40mil" at 304.985,192.786 h1.52
  text "3.5" at 321.49,192.786 h1.52
  text "3" at 248.865,189.738 h1.52
  text "Top Layer" at 259.277,189.738 h1.52
  text "Copper" at 283.146,189.738 h1.52
  text "1.40mil" at 304.985,189.738 h1.52
  text "4" at 248.865,186.69 h1.52
  text "Dielectric 1" at 259.277,186.69 h1.52
  text "FR-4" at 283.146,186.69 h1.52
  text "8.00mil" at 304.985,186.69 h1.52
  text "4.2" at 321.49,186.69 h1.52
  text "5" at 248.865,183.642 h1.52
  text "Signal Layer 1" at 259.277,183.642 h1.52
  text "Copper" at 283.146,183.642 h1.52
  text "1.40mil" at 304.985,183.642 h1.52
  text "6" at 248.865,180.594 h1.52
  text "Dielectric 2" at 259.277,180.594 h1.52
  text "FR-4" at 283.146,180.594 h1.52
  text "40.00mil" at 304.985,180.594 h1.52
  text "4.2" at 321.49,180.594 h1.52
  text "7" at 248.865,177.546 h1.52
  text "Signal Layer 2" at 259.277,177.546 h1.52
  text "Copper" at 283.146,177.546 h1.52
  text "1.40mil" at 304.985,177.546 h1.52
  text "8" at 248.865,174.498 h1.52
  text "Dielectric 3" at 259.277,174.498 h1.52
  text "FR-4" at 283.146,174.498 h1.52
  text "8.00mil" at 304.985,174.498 h1.52
  text "4.2" at 321.49,174.498 h1.52
  text "9" at 248.865,171.45 h1.52
  text "Bottom Layer" at 259.277,171.45 h1.52
  text "Copper" at 283.146,171.45 h1.52
  text "1.40mil" at 304.985,171.45 h1.52
  text "10" at 248.865,168.402 h1.52
  text "Bottom Solder" at 259.277,168.402 h1.52
  text "Solder Resist" at 283.146,168.402 h1.52
  text "0.40mil" at 304.985,168.402 h1.52
  text "3.5" at 321.49,168.402 h1.52
  text "11" at 248.865,165.354 h1.52
  text "Bottom Overlay" at 259.277,165.354 h1.52
  text ".Layer_Name" at 14.656,-21.806 h1.52
M13 Component Bodies Top:
  text ".Layer_Name" at 14.656,-21.806 h1.52
M14 Component Bodies Bottom:
  text ".Layer_Name" at 14.656,-21.806 h1.52
M15 Courtyards Top:
  text ".Layer_Name" at 14.656,-21.806 h1.52
M16 Courtyards Bottom:
  text ".Layer_Name" at 14.656,-21.806 h1.52
Drill Drawing:
  text ".Layer_Name" at 14.656,-21.806 h1.52
Mechanical 17:
  text ".Layer_Name" at 14.656,-21.806 h1.52
Mechanical 18:
  text ".Layer_Name" at 14.656,-21.806 h1.52
Mechanical 19:
  text ".Layer_Name" at 14.656,-21.806 h1.52

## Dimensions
0,-10.16 to 25.4,-10.16 on M2 Board Dimensions
0,0 to 0,100 on M2 Board Dimensions
0,0 to 140,0 on M2 Board Dimensions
